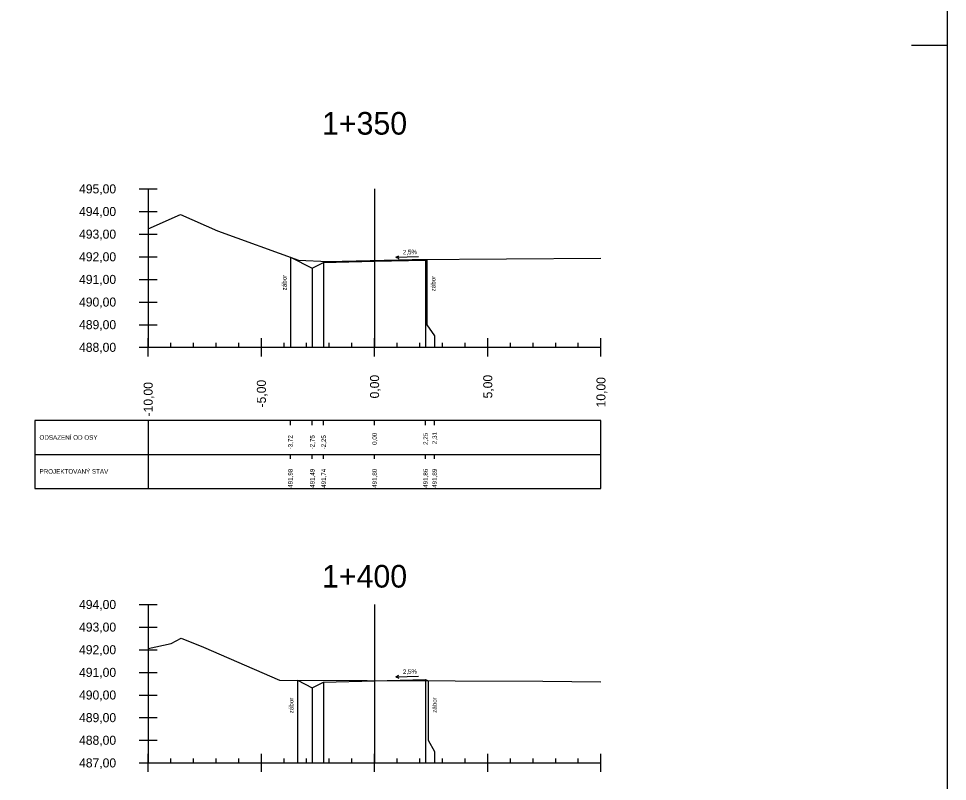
# Model space of a CAD drawing. Extents: x -631407 to -631215, y -1089700 to -1088598.
# Drawn here: x -631285.93 to -631244.9, y -1089530.26 to -1089496.55 of the extents above; entities that cross this region are included whole.
import ezdxf

# ---------------------------------------------------------------- set-up
doc = ezdxf.new("R2010")
doc.units = 0
for name, color, linetype in [('08_LEGENDA_HV', 7, 'Continuous'), ('59', 7, 'Continuous'), ('DTM-Breaklines', 7, 'Continuous'), ('NIVELETA_VYSKY', 7, 'Continuous'), ('REZ_BODY', 7, 'Continuous'), ('REZ_ODSTUPY', 7, 'Continuous'), ('REZ_POPIS', 7, 'Continuous'), ('REZ_RAMY', 7, 'Continuous'), ('REZ_STANICENI', 7, 'Continuous'), ('REZ_SVISLE', 7, 'Continuous'), ('REZ_TENKA', 7, 'Continuous'), ('REZ_TLUSTA', 7, 'Continuous'), ('TABULKA_POPIS', 7, 'Continuous'), ('TEREN', 7, 'Continuous'), ('zábor', 7, 'Continuous')]:
    doc.layers.add(name, color=color, linetype=linetype)

msp = doc.modelspace()

# ---------------------------------------------------------------- linework, layer by layer
at = {"layer": '08_LEGENDA_HV'}
msp.add_lwpolyline([(-631244.898, -1089557.13), (-631244.898, -1089438.33), (-631407.014, -1089438.33), (-631407.014, -1089557.13)], close=True, dxfattribs=at)
at = {"layer": '59'}
for p, q in [((-631280.602, -1089504.076), (-631279.802, -1089504.076)), ((-631280.202, -1089504.076), (-631280.202, -1089511.076)), ((-631280.602, -1089505.076), (-631279.802, -1089505.076)), ((-631280.602, -1089506.076), (-631279.802, -1089506.076)), ((-631280.602, -1089507.076), (-631279.802, -1089507.076)), ((-631280.602, -1089508.076), (-631279.802, -1089508.076)), ((-631280.602, -1089509.076), (-631279.802, -1089509.076)), ((-631280.602, -1089510.076), (-631279.802, -1089510.076)), ((-631280.602, -1089511.076), (-631279.802, -1089511.076)), ((-631280.602, -1089522.438), (-631279.802, -1089522.438)), ((-631280.202, -1089522.438), (-631280.202, -1089529.438)), ((-631280.602, -1089523.438), (-631279.802, -1089523.438)), ((-631280.602, -1089524.438), (-631279.802, -1089524.438)), ((-631280.602, -1089525.438), (-631279.802, -1089525.438)), ((-631280.602, -1089526.438), (-631279.802, -1089526.438)), ((-631280.602, -1089527.438), (-631279.802, -1089527.438)), ((-631280.602, -1089528.438), (-631279.802, -1089528.438)), ((-631280.602, -1089529.438), (-631279.802, -1089529.438))]:
    msp.add_line(p, q, dxfattribs=at)
at = {"layer": 'DTM-Breaklines'}
msp.add_line((-631246.479, -1089497.73), (-631244.898, -1089497.73), dxfattribs=at)
at = {"layer": 'REZ_RAMY'}
for p, q in [((-631285.202, -1089514.309), (-631285.202, -1089517.309)), ((-631280.202, -1089514.309), (-631280.202, -1089517.309)), ((-631273.92, -1089514.509), (-631273.92, -1089514.309)), ((-631272.952, -1089514.509), (-631272.952, -1089514.309)), ((-631272.452, -1089514.509), (-631272.452, -1089514.309)), ((-631270.202, -1089514.509), (-631270.202, -1089514.309)), ((-631267.952, -1089514.509), (-631267.952, -1089514.309)), ((-631267.552, -1089514.509), (-631267.552, -1089514.309)), ((-631285.202, -1089515.809), (-631260.202, -1089515.809)), ((-631273.92, -1089516.009), (-631273.92, -1089515.809)), ((-631272.952, -1089516.009), (-631272.952, -1089515.809)), ((-631272.452, -1089516.009), (-631272.452, -1089515.809)), ((-631270.202, -1089516.009), (-631270.202, -1089515.809)), ((-631267.952, -1089516.009), (-631267.952, -1089515.809)), ((-631267.552, -1089516.009), (-631267.552, -1089515.809))]:
    msp.add_line(p, q, dxfattribs=at)
msp.add_lwpolyline([(-631285.202, -1089514.309), (-631285.202, -1089517.309), (-631260.202, -1089517.309), (-631260.202, -1089514.309)], close=True, dxfattribs=at)
at = {"layer": 'REZ_SVISLE'}
for points in [[(-631273.92, -1089507.097), (-631273.92, -1089510.076), (-631273.92, -1089510.576), (-631273.92, -1089511.076)], [(-631272.452, -1089507.331), (-631272.452, -1089510.076), (-631272.452, -1089510.576), (-631272.452, -1089511.076)], [(-631270.202, -1089507.275), (-631270.202, -1089510.076), (-631270.202, -1089510.576), (-631270.202, -1089511.076)], [(-631267.952, -1089507.219), (-631267.952, -1089510.076), (-631267.952, -1089510.576), (-631267.952, -1089511.076)], [(-631267.895, -1089507.19), (-631267.895, -1089510.076), (-631267.552, -1089510.576), (-631267.552, -1089511.076)], [(-631272.952, -1089507.581), (-631272.952, -1089510.076), (-631272.952, -1089510.576), (-631272.952, -1089511.076)], [(-631273.613, -1089525.785), (-631273.613, -1089528.438), (-631273.613, -1089528.938), (-631273.613, -1089529.438)], [(-631272.452, -1089525.866), (-631272.452, -1089528.438), (-631272.452, -1089528.938), (-631272.452, -1089529.438)], [(-631270.202, -1089525.81), (-631270.202, -1089528.438), (-631270.202, -1089528.938), (-631270.202, -1089529.438)], [(-631267.952, -1089525.753), (-631267.952, -1089528.438), (-631267.952, -1089528.938), (-631267.952, -1089529.438)], [(-631267.836, -1089525.811), (-631267.836, -1089528.438), (-631267.552, -1089528.938), (-631267.552, -1089529.438)], [(-631272.952, -1089526.116), (-631272.952, -1089528.438), (-631272.952, -1089528.938), (-631272.952, -1089529.438)]]:
    msp.add_lwpolyline(points, dxfattribs=at)
at = {"layer": 'REZ_TENKA'}
for p, q in [((-631279.202, -1089511.076), (-631279.202, -1089510.876)), ((-631278.202, -1089511.076), (-631278.202, -1089510.876)), ((-631277.202, -1089511.076), (-631277.202, -1089510.876)), ((-631276.202, -1089511.076), (-631276.202, -1089510.876)), ((-631274.202, -1089511.076), (-631274.202, -1089510.876)), ((-631273.202, -1089511.076), (-631273.202, -1089510.876)), ((-631272.202, -1089511.076), (-631272.202, -1089510.876)), ((-631271.202, -1089511.076), (-631271.202, -1089510.876)), ((-631269.202, -1089511.076), (-631269.202, -1089510.876)), ((-631268.202, -1089511.076), (-631268.202, -1089510.876)), ((-631267.202, -1089511.076), (-631267.202, -1089510.876)), ((-631266.202, -1089511.076), (-631266.202, -1089510.876)), ((-631264.202, -1089511.076), (-631264.202, -1089510.876)), ((-631263.202, -1089511.076), (-631263.202, -1089510.876)), ((-631262.202, -1089511.076), (-631262.202, -1089510.876)), ((-631261.202, -1089511.076), (-631261.202, -1089510.876)), ((-631279.202, -1089529.438), (-631279.202, -1089529.238)), ((-631278.202, -1089529.438), (-631278.202, -1089529.238)), ((-631277.202, -1089529.438), (-631277.202, -1089529.238)), ((-631276.202, -1089529.438), (-631276.202, -1089529.238)), ((-631274.202, -1089529.438), (-631274.202, -1089529.238)), ((-631273.202, -1089529.438), (-631273.202, -1089529.238)), ((-631272.202, -1089529.438), (-631272.202, -1089529.238)), ((-631271.202, -1089529.438), (-631271.202, -1089529.238)), ((-631269.202, -1089529.438), (-631269.202, -1089529.238)), ((-631268.202, -1089529.438), (-631268.202, -1089529.238)), ((-631267.202, -1089529.438), (-631267.202, -1089529.238)), ((-631266.202, -1089529.438), (-631266.202, -1089529.238)), ((-631264.202, -1089529.438), (-631264.202, -1089529.238)), ((-631263.202, -1089529.438), (-631263.202, -1089529.238)), ((-631262.202, -1089529.438), (-631262.202, -1089529.238)), ((-631261.202, -1089529.438), (-631261.202, -1089529.238))]:
    msp.add_line(p, q, dxfattribs=at)
at = {"layer": 'REZ_TLUSTA'}
for p, q in [((-631270.202, -1089504.076), (-631270.202, -1089511.076)), ((-631280.202, -1089511.476), (-631280.202, -1089510.676)), ((-631275.202, -1089511.476), (-631275.202, -1089510.676)), ((-631270.202, -1089511.476), (-631270.202, -1089510.676)), ((-631265.202, -1089511.476), (-631265.202, -1089510.676)), ((-631260.202, -1089511.476), (-631260.202, -1089510.676)), ((-631280.202, -1089511.076), (-631260.202, -1089511.076)), ((-631270.202, -1089522.438), (-631270.202, -1089529.438)), ((-631280.202, -1089529.838), (-631280.202, -1089529.038)), ((-631275.202, -1089529.838), (-631275.202, -1089529.038)), ((-631270.202, -1089529.838), (-631270.202, -1089529.038)), ((-631265.202, -1089529.838), (-631265.202, -1089529.038)), ((-631260.202, -1089529.838), (-631260.202, -1089529.038)), ((-631280.202, -1089529.438), (-631260.202, -1089529.438))]:
    msp.add_line(p, q, dxfattribs=at)
at = {"layer": 'TEREN'}
for points in [[(-631280.202, -1089505.839), (-631278.773, -1089505.213), (-631277.14, -1089505.928), (-631273.562, -1089507.227), (-631272.257, -1089507.282), (-631268.548, -1089507.195), (-631260.202, -1089507.136)], [(-631273.92, -1089507.097), (-631272.952, -1089507.581), (-631272.452, -1089507.331), (-631270.202, -1089507.275), (-631267.952, -1089507.219), (-631267.895, -1089507.19)], [(-631280.202, -1089524.379), (-631279.189, -1089524.162), (-631278.748, -1089523.932), (-631277.759, -1089524.318), (-631274.4, -1089525.781), (-631262.764, -1089525.834), (-631260.202, -1089525.85)], [(-631273.613, -1089525.785), (-631272.952, -1089526.116), (-631272.452, -1089525.866), (-631270.202, -1089525.81), (-631267.952, -1089525.753), (-631267.836, -1089525.811)]]:
    msp.add_lwpolyline(points, dxfattribs=at)
at = {"layer": 'zábor'}
for p, q in [((-631269.269, -1089507.095), (-631269.132, -1089507.031)), ((-631269.269, -1089507.095), (-631268.261, -1089507.07)), ((-631269.269, -1089507.095), (-631269.129, -1089507.153)), ((-631269.269, -1089525.63), (-631269.132, -1089525.565)), ((-631269.269, -1089525.63), (-631268.261, -1089525.605)), ((-631269.269, -1089525.63), (-631269.129, -1089525.688))]:
    msp.add_line(p, q, dxfattribs=at)

# ---------------------------------------------------------------- texts
at = {"layer": 'NIVELETA_VYSKY'}
for s, p in [('491,98', (-631273.82, -1089517.285)), ('491,49', (-631272.852, -1089517.285)), ('491,74', (-631272.352, -1089517.285)), ('491,80', (-631270.102, -1089517.285)), ('491,86', (-631267.852, -1089517.285)), ('491,89', (-631267.452, -1089517.285))]:
    msp.add_text(s, height=0.2, rotation=90, dxfattribs=at).set_placement(p)
at = {"layer": 'REZ_BODY'}
for s, p in [('0,00', (-631270.102, -1089515.388)), ('2,25', (-631267.852, -1089515.388)), ('2,31', (-631267.452, -1089515.355)), ('-3,72', (-631273.82, -1089515.587)), ('-2,75', (-631272.852, -1089515.587)), ('-2,25', (-631272.352, -1089515.587))]:
    msp.add_text(s, height=0.2, rotation=90, dxfattribs=at).set_placement(p)
at = {"layer": 'REZ_ODSTUPY'}
for s, p in [('0,00', (-631270.002, -1089513.334)), ('5,00', (-631265.002, -1089513.334)), ('10,00', (-631260.002, -1089513.731)), ('-10,00', (-631280.002, -1089514.128)), ('-5,00', (-631275.002, -1089513.731))]:
    msp.add_text(s, height=0.4, rotation=90, dxfattribs=at).set_placement(p)
at = {"layer": 'REZ_POPIS'}
for s, p in [('495,00', (-631283.254, -1089504.276)), ('494,00', (-631283.254, -1089505.276)), ('493,00', (-631283.254, -1089506.276)), ('492,00', (-631283.254, -1089507.276)), ('491,00', (-631283.254, -1089508.276)), ('490,00', (-631283.254, -1089509.276)), ('489,00', (-631283.254, -1089510.276)), ('488,00', (-631283.254, -1089511.276)), ('494,00', (-631283.254, -1089522.638)), ('493,00', (-631283.254, -1089523.638)), ('492,00', (-631283.254, -1089524.638)), ('491,00', (-631283.254, -1089525.638)), ('490,00', (-631283.254, -1089526.638)), ('489,00', (-631283.254, -1089527.638)), ('488,00', (-631283.254, -1089528.638)), ('487,00', (-631283.254, -1089529.638))]:
    msp.add_text(s, height=0.4, dxfattribs=at).set_placement(p)
at = {"layer": 'REZ_STANICENI'}
for s, p in [('1+350', (-631272.52, -1089501.679)), ('1+400', (-631272.52, -1089521.692))]:
    msp.add_text(s, height=1, dxfattribs=at).set_placement(p)
at = {"layer": 'TABULKA_POPIS'}
for s, p in [('ODSAZENÍ OD OSY', (-631285.002, -1089515.159)), ('PROJEKTOVANÝ STAV', (-631285.002, -1089516.659))]:
    msp.add_text(s, height=0.2, dxfattribs=at).set_placement(p)
at = {"layer": 'zábor'}
for s, rotation, p in [('2,5%', 1.4321, (-631268.952, -1089506.974)), ('zábor', 90, (-631274.09, -1089508.561)), ('zábor', 90, (-631267.512, -1089508.605)), ('2,5%', 1.4321, (-631268.952, -1089525.509)), ('zábor', 90, (-631273.784, -1089527.248)), ('zábor', 90, (-631267.454, -1089527.225))]:
    msp.add_text(s, height=0.2, rotation=rotation, dxfattribs=at).set_placement(p)

doc.saveas('drawing.dxf')
